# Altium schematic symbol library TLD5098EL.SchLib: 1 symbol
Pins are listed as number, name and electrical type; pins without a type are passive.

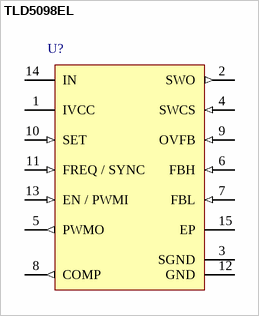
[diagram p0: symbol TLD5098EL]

## TLD5098EL
designator U?
Multitopology High Power LED DC/DC IC, 4.5 to 45 V, PG-SSOP-14, Reel, Pb-free; Manufacturer: Infineon; PartNumber: TLD5098EL; Green: TRUE; Topology: DC-DC Boost, Buck, Sepic, Buck-Boost, Flyback; VS (max): 45 V; VS (min): 4.5 V
footprint INF-PG-SSOP-14_N (SOP, 14-Leads, Body 4.9x3.9mm, Pitch 0.65mm, Thermal Pad 3.2x2.75mm, IPC Medium Density)
footprint INF-PG-SSOP-14_L (SOP, 14-Leads, Body 4.9x3.9mm, Pitch 0.65mm, Thermal Pad 3.2x2.85mm, IPC High Density)
footprint INF-PG-SSOP-14_M (SOP, 14-Leads, Body 4.9x3.9mm, Pitch 0.65mm, Thermal Pad 3.2x2.55mm, IPC Low Density)
pins: 1 IVCC (power) "Internal LDO Output; Used for internal biasing and gate drive. Bypass with external capacitor close to the pin. Pin must not be left open.", 2 SWO (out) "Switch Output; Connect to gate of external switching MOSFET", 3 SGND (power) "Current Sense Ground; Ground return for current sense switch", 4 SWCS (in) "Current Sense Input; Detects the peak current through switch", 5 PWMO (out) "PWM Dimming Output; Connect to gate of external MOSFET", 6 FBH (in) "Voltage Feedback Positive; Non inverting Input (+)", 7 FBL (in) "Voltage Feedback Negative; Inverting Input (-)", 8 COMP (out) "Compensation Input; Connect R and C network to pin for stability", 9 OVFB (in) "Output Overvoltage Protection Feedback; Connect to resistive voltage divider to set overvoltage threshold.", 10 SET (in) "Analog Dimming Input; Load current adjustment Pin. Pin must not be left open. If analog dimming feature is not used connect to IVCC pin.", 11 FREQ / SYNC (in) "Frequency Select or Synchronization Input; Connect external resistor to GND to set frequency. Or apply external clock signal for synchronization within frequency capture range.", 12 GND (power) "Ground; Connect to system ground.", 13 EN / PWMI (in) "Enable or PWM Input; Apply logic HIGH signal to enable device or PWM signal for dimming LED.", 14 IN (power) "Supply Input; Supply for internal biasing.", 15 EP (power) "Exposed Pad; Connect to external heatspreading GND Cu area (e.g. inner GND layer of multilayer PCB with thermal vias)."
